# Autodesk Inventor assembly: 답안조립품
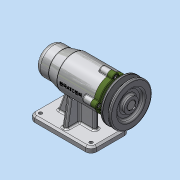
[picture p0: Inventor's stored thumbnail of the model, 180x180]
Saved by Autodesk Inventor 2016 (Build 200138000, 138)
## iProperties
Created: 2019-07
Part Number: 답안조립품
Document SubType Name: Assembly
Designer: MIRAE
Author: MIRAE
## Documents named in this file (12)
- C:\Users\MIRAE\Desktop\490704V1062\답안조립품.iam
- C:\Users\MIRAE\Desktop\490704V1062\본체.ipt
- C:\Users\MIRAE\Desktop\490704V1062\축.ipt
- C:\Users\MIRAE\Desktop\490704V1062\베어링 6004.ipt
- C:\Users\MIRAE\Desktop\490704V1062\볼트 M4.ipt
- C:\Users\MIRAE\Desktop\490704V1062\어댑터슬리브.ipt
- C:\Users\MIRAE\Desktop\490704V1062\베어링 51202.ipt
- C:\Users\MIRAE\Desktop\490704V1062\오일 실.ipt
- C:\Users\MIRAE\Desktop\490704V1062\커버.ipt
- C:\Users\MIRAE\Desktop\490704V1062\V벨트풀리.ipt
- C:\Users\MIRAE\Desktop\490704V1062\멈춤나사 M3.ipt
- C:\Users\MIRAE\Desktop\490704V1062\키 5 x 5 x 16.ipt
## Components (1 placed, 1 different names)
1. V벨트풀리:1
